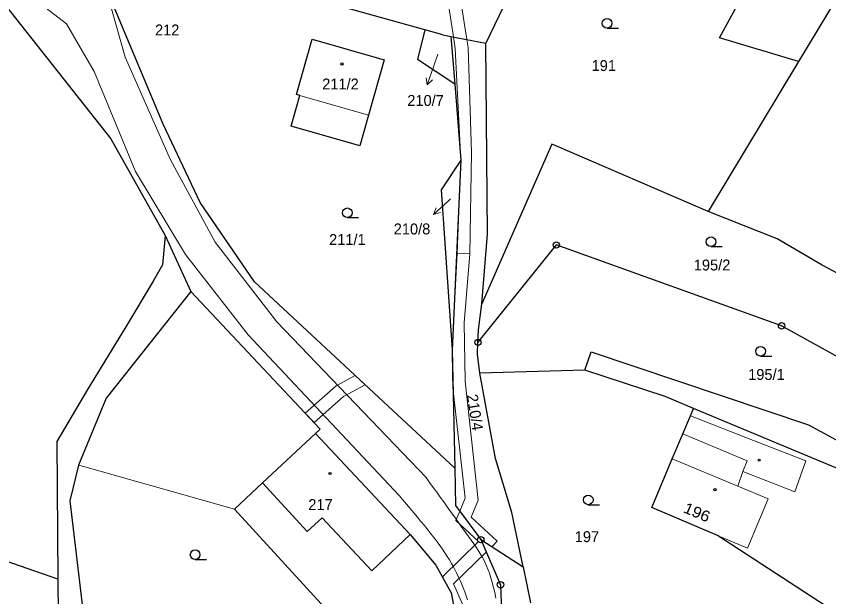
# Model space of a CAD drawing. Extents: x -504006 to -501322, y -1128098 to -1124665.
# Drawn here: x -502675.9 to -502549.5, y -1126704.2 to -1126613.8 of the extents above; entities that cross this region are included whole.
import ezdxf
from ezdxf.enums import TextEntityAlignment as Align

# ---------------------------------------------------------------- set-up
doc = ezdxf.new("R2010")
doc.units = 0
doc.header["$LTSCALE"] = 0.68
for name, color, linetype, lineweight in [('1', 7, 'Continuous', 25), ('13', 7, 'Continuous', 13), ('3', 7, 'Continuous', 25), ('4', 7, 'Continuous', 13), ('5', 7, 'Continuous', 25), ('7', 7, 'Continuous', 13), ('8', 7, 'Continuous', 25)]:
    doc.layers.add(name, color=color, linetype=linetype, lineweight=lineweight)
doc.layers.add('2', color=7, linetype='Continuous')

msp = doc.modelspace()

# ---------------------------------------------------------------- linework, layer by layer
at = {"layer": '1'}
for p, q in [((-502583.59, -1126577.84), (-502602.88, -1126618)), ((-502544.95, -1126605.46), (-502554.24, -1126620.87)), ((-502566.52, -1126617.2), (-502562.03, -1126608.89)), ((-502679.44, -1126609.85), (-502661.24, -1126632.88)), ((-502653.09, -1126630.62), (-502660.6, -1126612.65)), ((-502612.36, -1126615.94), (-502613.54, -1126620.54)), ((-502609.57, -1126616.72), (-502612.36, -1126615.94)), ((-502632.35, -1126626), (-502629.91, -1126617.41)), ((-502629.91, -1126617.41), (-502618.69, -1126620.62)), ((-502609.57, -1126616.72), (-502608.31, -1126616.96)), ((-502608.31, -1126616.96), (-502607.73, -1126624.39)), ((-502608.31, -1126616.96), (-502602.88, -1126618)), ((-502554.24, -1126620.87), (-502566.52, -1126617.2)), ((-502602.64, -1126647.73), (-502602.88, -1126618)), ((-502618.69, -1126620.62), (-502621.14, -1126629.2)), ((-502607.73, -1126624.39), (-502613.54, -1126620.54)), ((-502554.24, -1126620.87), (-502568.3, -1126644.22)), ((-502607.73, -1126624.39), (-502606.78, -1126636.21)), ((-502633.18, -1126630.95), (-502631.82, -1126626.15)), ((-502631.82, -1126626.15), (-502632.35, -1126626)), ((-502621.14, -1126629.2), (-502622.51, -1126634)), ((-502647.35, -1126642.83), (-502653.09, -1126630.62)), ((-502622.51, -1126634), (-502633.18, -1126630.95)), ((-502661.24, -1126632.88), (-502652.77, -1126647.95)), ((-502592.61, -1126633.73), (-502603.51, -1126658.6)), ((-502592.11, -1126633.95), (-502592.61, -1126633.73)), ((-502606.78, -1126636.21), (-502609.84, -1126640.84)), ((-502606.78, -1126636.21), (-502608.15, -1126665.75)), ((-502609.84, -1126640.84), (-502608.15, -1126665.75)), ((-502638.88, -1126655.14), (-502647.35, -1126642.83)), ((-502652.77, -1126647.95), (-502653.21, -1126652.5)), ((-502652.77, -1126647.95), (-502648.78, -1126656.68)), ((-502603.51, -1126658.6), (-502602.64, -1126647.73)), ((-502550.55, -1126652.54), (-502557.54, -1126648.44)), ((-502591.92, -1126649.42), (-502604.11, -1126664.57)), ((-502556.87, -1126662.01), (-502591.92, -1126649.42)), ((-502653.21, -1126652.5), (-502654.63, -1126655.07)), ((-502540.59, -1126658), (-502550.55, -1126652.54)), ((-502654.63, -1126655.07), (-502658.88, -1126662.15)), ((-502607.72, -1126684.15), (-502638.88, -1126655.14)), ((-502648.78, -1126656.68), (-502661.94, -1126673.26)), ((-502648.78, -1126656.68), (-502628.66, -1126678.08)), ((-502525.52, -1126679.45), (-502556.87, -1126662.01)), ((-502658.88, -1126662.15), (-502664.85, -1126671.93)), ((-502608.15, -1126665.75), (-502607.72, -1126684.15)), ((-502604.16, -1126666.4), (-502604.11, -1126664.57)), ((-502603.84, -1126669.35), (-502604.16, -1126666.4)), ((-502587.46, -1126668.88), (-502586.51, -1126666.03)), ((-502586.51, -1126666.03), (-502552.7, -1126677.43)), ((-502587.46, -1126668.88), (-502603.84, -1126669.35)), ((-502601.36, -1126682.64), (-502603.84, -1126669.35)), ((-502574.99, -1126673.01), (-502587.46, -1126668.88)), ((-502664.85, -1126671.93), (-502669.62, -1126680.03)), ((-502661.94, -1126673.26), (-502666.24, -1126683.69)), ((-502570.56, -1126674.86), (-502574.99, -1126673.01)), ((-502571.04, -1126676), (-502570.56, -1126674.86)), ((-502535.97, -1126689.29), (-502570.56, -1126674.86)), ((-502572.24, -1126678.83), (-502571.04, -1126676)), ((-502628.66, -1126678.08), (-502629.39, -1126678.76)), ((-502552.7, -1126677.43), (-502530.11, -1126689.67)), ((-502637.61, -1126686.45), (-502629.39, -1126678.76)), ((-502629.39, -1126678.76), (-502614.64, -1126694.5)), ((-502573.88, -1126682.7), (-502572.24, -1126678.83)), ((-502669.62, -1126680.03), (-502669.46, -1126701.42)), ((-502598.86, -1126691.04), (-502601.36, -1126682.64)), ((-502577.08, -1126690.26), (-502573.88, -1126682.7)), ((-502666.24, -1126683.69), (-502667.59, -1126689.22)), ((-502607.72, -1126684.15), (-502607.59, -1126689.95)), ((-502642, -1126690.55), (-502637.61, -1126686.45)), ((-502667.59, -1126689.22), (-502664.19, -1126717.79)), ((-502624.72, -1126709.35), (-502642, -1126690.55)), ((-502607.59, -1126689.95), (-502603.68, -1126695.28)), ((-502597.1, -1126699.5), (-502598.86, -1126691.04)), ((-502566.86, -1126694.62), (-502577.08, -1126690.26)), ((-502669.46, -1126701.42), (-502697.98, -1126691.57)), ((-502614.64, -1126694.5), (-502610.66, -1126699.23)), ((-502545.88, -1126708.26), (-502566.86, -1126694.62)), ((-502603.68, -1126695.28), (-502600.61, -1126702.3)), ((-502610.66, -1126699.23), (-502608.28, -1126703.54)), ((-502669.46, -1126701.42), (-502669.34, -1126718.51)), ((-502600.61, -1126702.3), (-502600.46, -1126706.4)), ((-502608.28, -1126703.54), (-502607.58, -1126707.12))]:
    msp.add_line(p, q, dxfattribs=at)
for points in [[(-502612.36, -1126615.94), (-502652.82, -1126604.6), (-502660.6, -1126612.65)], [(-502557.54, -1126648.44), (-502568.3, -1126644.22), (-502592.11, -1126633.95)], [(-502604.11, -1126664.57), (-502604.05, -1126662.62), (-502603.51, -1126658.6)], [(-502603.68, -1126695.28), (-502597.1, -1126699.5), (-502595.93, -1126705.13)]]:
    msp.add_lwpolyline(points, dxfattribs=at)
at = {"layer": '13'}
for points in [[(-502609.03, -1126609.98), (-502607.93, -1126617.03), (-502607.65, -1126618.85), (-502606.78, -1126636.21), (-502607.37, -1126650.68), (-502605.37, -1126650.78), (-502605.14, -1126635.05), (-502605.65, -1126618.67), (-502605.84, -1126617.43), (-502607.14, -1126609.14)], [(-502605.71, -1126707.2), (-502607.9, -1126702.14), (-502602.83, -1126697.22), (-502603.68, -1126695.28), (-502601.97, -1126696.38), (-502601.1, -1126695.54), (-502605.18, -1126691.8), (-502604.06, -1126689.12), (-502606.09, -1126670.64), (-502606.28, -1126661.56), (-502605.37, -1126650.78), (-502607.37, -1126650.68), (-502608.15, -1126665.75), (-502608.06, -1126669.61), (-502608.01, -1126671.62), (-502606.1, -1126688.82), (-502606.94, -1126690.83), (-502607.56, -1126692.32), (-502604.02, -1126695.58), (-502609.65, -1126701.05), (-502608.28, -1126703.54), (-502607.58, -1126707.12)]]:
    msp.add_lwpolyline(points, dxfattribs=at)
msp.add_lwpolyline([(-502623.19, -1126669.75), (-502626.18, -1126671.32), (-502630.98, -1126675.62), (-502629.61, -1126677.07), (-502625.03, -1126672.98), (-502621.64, -1126671.19)], close=True, dxfattribs=at)
at = {"layer": '3'}
for p, q in [((-502584.023, -1126615.68), (-502582.273, -1126615.68)), ((-502624.423, -1126645.16), (-502622.673, -1126645.16)), ((-502567.853, -1126649.67), (-502566.103, -1126649.67)), ((-502560.143, -1126666.72), (-502558.393, -1126666.72)), ((-502586.953, -1126689.84), (-502585.203, -1126689.84)), ((-502648.113, -1126698.38), (-502646.363, -1126698.38))]:
    msp.add_line(p, q, dxfattribs=at)
for centre in [(-502584.0229, -1126614.9298), (-502624.4229, -1126644.4098), (-502567.8529, -1126648.9198), (-502560.1429, -1126665.9698), (-502586.9529, -1126689.0898), (-502648.1129, -1126697.6298)]:
    msp.add_circle(centre, 0.75, dxfattribs=at)
at = {"layer": '4'}
for p, q in [((-502668.1, -1126615), (-502674.8, -1126609.85)), ((-502659, -1126620.2), (-502662.14, -1126608.95)), ((-502663.8, -1126622.4), (-502668.1, -1126615)), ((-502651.95, -1126636.18), (-502659, -1126620.2)), ((-502657.4, -1126637.99), (-502663.8, -1126622.4)), ((-502631.82, -1126626.15), (-502621.14, -1126629.2)), ((-502645, -1126649), (-502651.95, -1126636.18)), ((-502649.6, -1126650.9), (-502657.4, -1126637.99)), ((-502635.4, -1126661.4), (-502645, -1126649)), ((-502639.85, -1126663.4), (-502649.6, -1126650.9)), ((-502612.18, -1126685.6), (-502635.4, -1126661.4)), ((-502616.38, -1126688.4), (-502639.85, -1126663.4)), ((-502571.04, -1126676), (-502561.24, -1126679.83)), ((-502562.25, -1126683.03), (-502572.24, -1126678.83)), ((-502561.24, -1126679.83), (-502553.11, -1126683.01)), ((-502573.88, -1126682.7), (-502563.7, -1126686.95)), ((-502562.89, -1126684.65), (-502562.25, -1126683.03)), ((-502553.11, -1126683.01), (-502554.84, -1126687.86)), ((-502666.24, -1126683.69), (-502665.27, -1126683.96)), ((-502665.27, -1126683.96), (-502642, -1126690.55)), ((-502562.89, -1126684.65), (-502563.7, -1126686.95)), ((-502554.84, -1126687.86), (-502562.89, -1126684.65)), ((-502630.68, -1126694.03), (-502637.61, -1126686.45)), ((-502563.7, -1126686.95), (-502558.98, -1126688.92)), ((-502558.98, -1126688.92), (-502562.19, -1126696.61)), ((-502628.33, -1126691.88), (-502630.68, -1126694.03)), ((-502620.64, -1126700.16), (-502628.33, -1126691.88)), ((-502614.64, -1126694.5), (-502620.64, -1126700.16)), ((-502562.19, -1126696.61), (-502566.86, -1126694.62))]:
    msp.add_line(p, q, dxfattribs=at)
for points in [[(-502601.338, -1126704.382), (-502601.508, -1126703.532), (-502601.69, -1126702.718), (-502601.889, -1126701.933), (-502602.1, -1126701.2), (-502602.327, -1126700.512), (-502602.574, -1126699.856), (-502602.835, -1126699.242), (-502603.113, -1126698.656), (-502603.412, -1126698.084), (-502603.725, -1126697.535), (-502604.056, -1126696.995), (-502604.41, -1126696.451), (-502604.778, -1126695.911), (-502605.164, -1126695.361), (-502605.575, -1126694.788), (-502606, -1126694.2), (-502606.444, -1126693.585), (-502606.912, -1126692.937), (-502607.39, -1126692.273), (-502607.883, -1126691.588), (-502608.396, -1126690.875), (-502608.913, -1126690.155), (-502609.441, -1126689.42), (-502609.983, -1126688.665), (-502610.525, -1126687.909), (-502611.071, -1126687.147), (-502611.628, -1126686.37), (-502612.18, -1126685.6)], [(-502605.744, -1126704.623), (-502605.952, -1126704.002), (-502606.173, -1126703.389), (-502606.4, -1126702.8), (-502606.632, -1126702.227), (-502606.874, -1126701.661), (-502607.122, -1126701.112), (-502607.381, -1126700.573), (-502607.655, -1126700.032), (-502607.939, -1126699.5), (-502608.24, -1126698.968), (-502608.561, -1126698.427), (-502608.899, -1126697.887), (-502609.257, -1126697.339), (-502609.644, -1126696.773), (-502610.05, -1126696.2), (-502610.482, -1126695.611), (-502610.944, -1126694.999), (-502611.423, -1126694.381), (-502611.921, -1126693.751), (-502612.444, -1126693.101), (-502612.975, -1126692.45), (-502613.52, -1126691.79), (-502614.083, -1126691.116), (-502614.648, -1126690.444), (-502615.219, -1126689.768), (-502615.802, -1126689.08), (-502616.38, -1126688.4)]]:
    msp.add_lwpolyline(points, dxfattribs=at)
at = {"layer": '5'}
for centre in [(-502625.2768, -1126621.2492), (-502560.3668, -1126682.9092), (-502627.1168, -1126684.9892), (-502567.2468, -1126687.4992)]:
    msp.add_circle(centre, 0.175, dxfattribs=at)
at = {"layer": '7'}
for p, q in [((-502612.007, -1126624.507), (-502611.208, -1126623.724)), ((-502611.005, -1126644.677), (-502609.931, -1126644.36))]:
    msp.add_line(p, q, dxfattribs=at)
for points in [[(-502610.37, -1126619.74), (-502611.03, -1126621.67), (-502612.007, -1126624.507), (-502612.154, -1126623.398)], [(-502608.37, -1126642.22), (-502608.81, -1126642.63), (-502611.005, -1126644.677), (-502610.614, -1126643.627)]]:
    msp.add_lwpolyline(points, dxfattribs=at)
at = {"layer": '8'}
for centre, radius in [((-502591.92, -1126649.4199), 0.5), ((-502591.92, -1126649.4199), 0.0303), ((-502556.87, -1126662.0099), 0.5), ((-502556.87, -1126662.0099), 0.0303), ((-502604.11, -1126664.5699), 0.5), ((-502604.11, -1126664.5699), 0.0303), ((-502603.68, -1126695.2799), 0.5), ((-502603.68, -1126695.2799), 0.0303), ((-502600.61, -1126702.2999), 0.5), ((-502600.61, -1126702.2999), 0.0303)]:
    msp.add_circle(centre, radius, dxfattribs=at)

# ---------------------------------------------------------------- texts
at = {"layer": '2'}
for s, p in [('212', (-502652.459, -1126616.805)), ('191', (-502584.539, -1126622.345)), ('211/2', (-502625.5, -1126625.215)), ('210/7', (-502612.26, -1126627.775)), ('211/1', (-502624.43, -1126649.425)), ('195/2', (-502567.69, -1126653.385)), ('195/1', (-502559.23, -1126670.425)), ('217', (-502628.609, -1126690.675)), ('197', (-502587.159, -1126695.665))]:
    msp.add_text(s, height=1.7, dxfattribs=at).set_placement(p, align=Align.CENTER)
msp.add_text('210/8', height=1.7, dxfattribs=at).set_placement((-502611.53, -1126647.775), align=Align.RIGHT)
msp.add_text('210/4', height=1.7, rotation=279, dxfattribs=at).set_placement((-502605.4086, -1126675.604), align=Align.CENTER)
at = {"layer": '2', "width": 1.1}
msp.add_text('196', height=1.7, rotation=337, dxfattribs=at).set_placement((-502570.3661, -1126691.8027), align=Align.CENTER)

doc.saveas('drawing.dxf')
